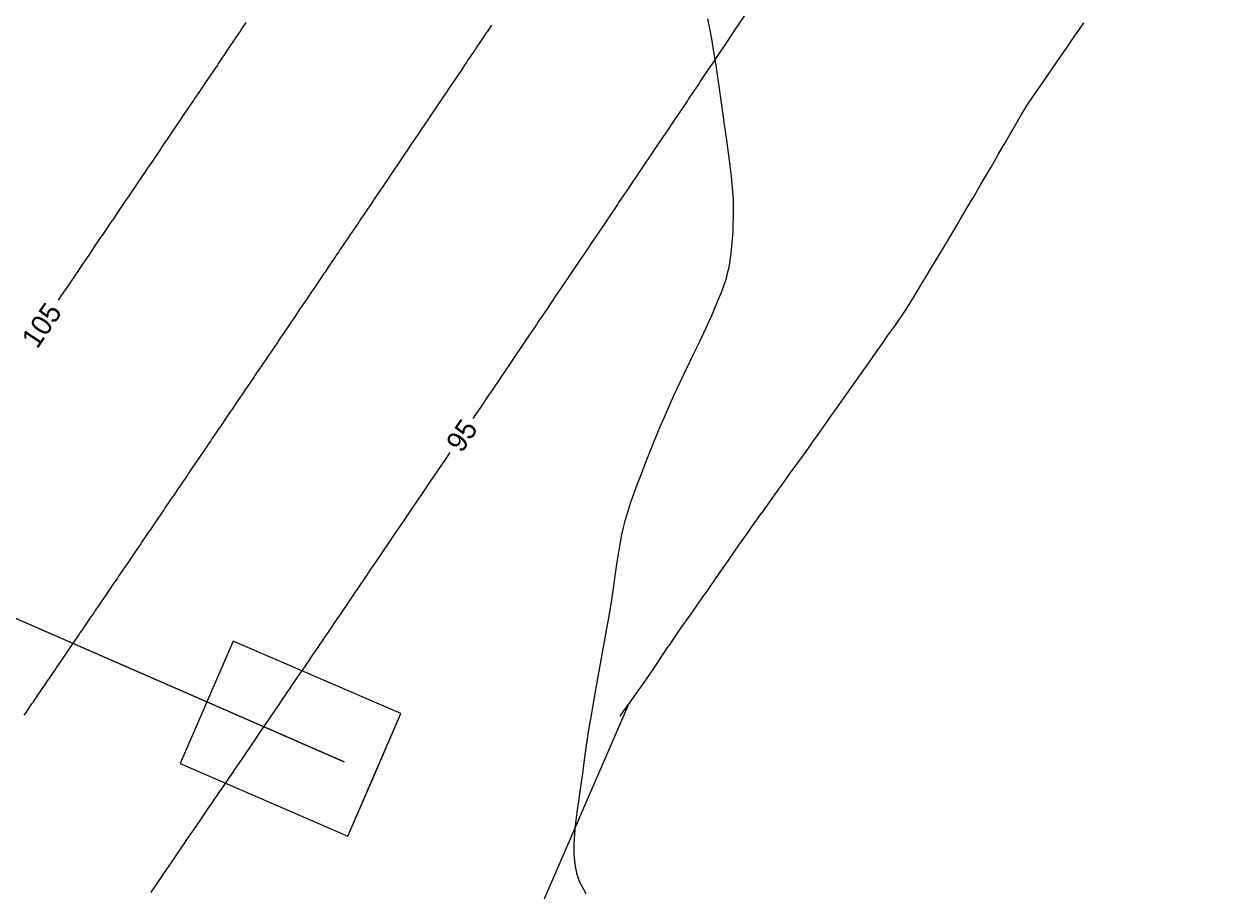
# Model space of a CAD drawing. Extents: x 1752788 to 1754108, y 472767 to 474963.
# Drawn here: x 1753280 to 1753338.7, y 473747.6 to 473789.9 of the extents above; entities that cross this region are included whole.
import ezdxf

# ---------------------------------------------------------------- set-up
doc = ezdxf.new("R2010")
doc.units = 0
for name, color, linetype in [('D_Drainage_Culvert', 7, 'Continuous'), ('D_Roadway_Centerline', 7, 'Continuous'), ('D_Slope_ClearingLimitLine', 7, 'Continuous'), ('Default', 7, 'Continuous'), ('M_Drainage_Ditch_Line', 7, 'Continuous'), ('PATTERNING', 7, 'Continuous'), ('S_Contours_Major', 7, 'Continuous')]:
    doc.layers.add(name, color=color, linetype=linetype)

msp = doc.modelspace()

# ---------------------------------------------------------------- linework, layer by layer
at = {"layer": 'D_Drainage_Culvert'}
msp.add_line((1753148.958, 473817.925), (1753295.6, 473753.923), dxfattribs=at)
at = {"layer": 'D_Roadway_Centerline'}
msp.add_arc((1748084.974, 477769.754), 6500, 316.3419444, 334.4169444, dxfattribs=at)
at = {"layer": 'D_Slope_ClearingLimitLine'}
msp.add_line((1753303.72, 473743.478), (1753309.439, 473756.699), dxfattribs=at)
msp.add_lwpolyline([(1753309.039, 473756.141), (1753309.222, 473756.398), (1753309.581, 473756.898), (1753309.969, 473757.443), (1753310.285, 473757.901), (1753310.725, 473758.55), (1753310.889, 473758.794), (1753311.387, 473759.533), (1753311.44, 473759.61), (1753311.966, 473760.382), (1753312.498, 473761.141), (1753312.608, 473761.296), (1753313.089, 473761.981), (1753313.307, 473762.293), (1753313.689, 473762.842), (1753313.983, 473763.266), (1753314.265, 473763.671), (1753314.642, 473764.213), (1753314.825, 473764.475), (1753315.287, 473765.132), (1753315.371, 473765.252), (1753315.931, 473766.038), (1753315.935, 473766.044), (1753316.521, 473766.861), (1753316.599, 473766.97), (1753317.107, 473767.678), (1753317.28, 473767.918), (1753317.698, 473768.501), (1753317.966, 473768.874), (1753318.293, 473769.329), (1753318.417, 473769.503), (1753318.681, 473769.875), (1753318.915, 473770.205), (1753319.361, 473770.837), (1753319.5, 473771.032), (1753320.038, 473771.793), (1753320.084, 473771.858), (1753320.669, 473772.685), (1753320.717, 473772.753), (1753321.264, 473773.528), (1753321.406, 473773.729), (1753321.85, 473774.36), (1753322.073, 473774.676), (1753322.448, 473775.208), (1753322.962, 473775.949), (1753323.36, 473776.603), (1753323.738, 473777.226), (1753323.898, 473777.49), (1753324.357, 473778.251), (1753324.434, 473778.38), (1753324.966, 473779.265), (1753324.985, 473779.295), (1753325.505, 473780.168), (1753325.612, 473780.348), (1753326.051, 473781.093), (1753326.234, 473781.406), (1753326.585, 473782.008), (1753326.843, 473782.451), (1753327.109, 473782.91), (1753327.443, 473783.488), (1753327.624, 473783.801), (1753327.794, 473784.095), (1753328.034, 473784.511), (1753328.134, 473784.683), (1753328.577, 473785.45), (1753328.9, 473785.977), (1753329.328, 473786.597), (1753329.487, 473786.828), (1753329.902, 473787.431), (1753330.151, 473787.793), (1753330.477, 473788.265), (1753330.816, 473788.758), (1753331.051, 473789.099), (1753331.481, 473789.723), (1753331.626, 473789.934)], dxfattribs=at)
at = {"layer": 'Default'}
msp.add_line((1753295.6, 473753.923), (1753145.826, 473819.295), dxfattribs=at)
at = {"layer": 'M_Drainage_Ditch_Line'}
msp.add_lwpolyline([(1753313.289, 473790.142), (1753313.388, 473789.663), (1753313.483, 473789.152), (1753313.575, 473788.619), (1753313.663, 473788.072), (1753313.747, 473787.52), (1753313.826, 473786.972), (1753313.974, 473785.92), (1753314.105, 473784.988), (1753314.199, 473784.338), (1753314.304, 473783.605), (1753314.356, 473783.222), (1753314.405, 473782.836), (1753314.45, 473782.453), (1753314.489, 473782.078), (1753314.519, 473781.717), (1753314.54, 473781.377), (1753314.55, 473781.063), (1753314.55, 473780.772), (1753314.547, 473780.455), (1753314.538, 473780.118), (1753314.523, 473779.768), (1753314.501, 473779.41), (1753314.472, 473779.051), (1753314.434, 473778.695), (1753314.387, 473778.35), (1753314.33, 473778.021), (1753314.262, 473777.714), (1753314.183, 473777.436), (1753313.986, 473776.88), (1753313.751, 473776.286), (1753313.484, 473775.663), (1753313.193, 473775.018), (1753312.887, 473774.362), (1753312.572, 473773.703), (1753311.952, 473772.412), (1753311.662, 473771.797), (1753311.396, 473771.214), (1753311.162, 473770.673), (1753310.997, 473770.279), (1753310.634, 473769.395), (1753310.442, 473768.921), (1753310.249, 473768.434), (1753310.057, 473767.942), (1753309.872, 473767.452), (1753309.697, 473766.972), (1753309.535, 473766.508), (1753309.391, 473766.068), (1753309.269, 473765.66), (1753309.187, 473765.343), (1753309.11, 473764.996), (1753309.04, 473764.626), (1753308.973, 473764.239), (1753308.911, 473763.841), (1753308.852, 473763.44), (1753308.69, 473762.277), (1753308.638, 473761.924), (1753308.587, 473761.601), (1753308.473, 473760.944), (1753308.347, 473760.232), (1753307.921, 473757.888), (1753307.776, 473757.077), (1753307.636, 473756.272), (1753307.505, 473755.485), (1753307.386, 473754.728), (1753307.284, 473754.012), (1753307.201, 473753.352), (1753307.146, 473752.932), (1753307.078, 473752.473), (1753307.004, 473751.982), (1753306.931, 473751.469), (1753306.865, 473750.945), (1753306.815, 473750.419), (1753306.788, 473749.901), (1753306.79, 473749.4), (1753306.829, 473748.926), (1753306.911, 473748.49), (1753307.046, 473748.1), (1753307.369, 473747.504)], dxfattribs=at)
at = {"layer": 'PATTERNING'}
for points in [[(1753297.068, 473753.287), (1753298.358, 473756.27), (1753290.19, 473759.804), (1753287.609, 473753.838), (1753295.778, 473750.304)], [(1753287.609, 473753.838), (1753295.778, 473750.304), (1753298.358, 473756.27), (1753290.19, 473759.804)]]:
    msp.add_lwpolyline(points, close=True, dxfattribs=at)
at = {"layer": 'S_Contours_Major'}
for points in [[(1753301.875, 473770.646), (1753302.124, 473771.013), (1753302.182, 473771.099), (1753302.691, 473771.853), (1753302.749, 473771.938), (1753303.259, 473772.692), (1753303.317, 473772.778), (1753303.826, 473773.531), (1753303.884, 473773.617), (1753304.392, 473774.37), (1753304.451, 473774.457), (1753304.959, 473775.209), (1753305.018, 473775.296), (1753305.526, 473776.048), (1753305.585, 473776.136), (1753306.092, 473776.887), (1753306.152, 473776.976), (1753306.659, 473777.727), (1753306.718, 473777.815), (1753306.815, 473777.959), (1753307.238, 473778.587), (1753307.283, 473778.652), (1753307.791, 473779.406), (1753307.851, 473779.495), (1753308.357, 473780.246), (1753308.417, 473780.335), (1753308.923, 473781.086), (1753308.983, 473781.175), (1753309.488, 473781.926), (1753309.549, 473782.016), (1753310.054, 473782.766), (1753310.115, 473782.856), (1753310.62, 473783.606), (1753310.681, 473783.696), (1753311.185, 473784.446), (1753311.246, 473784.537), (1753311.751, 473785.287), (1753311.811, 473785.377), (1753312.317, 473786.128), (1753312.376, 473786.217), (1753312.882, 473786.97), (1753312.941, 473787.058), (1753313.448, 473787.812), (1753313.506, 473787.898), (1753314.014, 473788.654), (1753314.071, 473788.739), (1753314.579, 473789.496), (1753314.635, 473789.579), (1753315.145, 473790.339)], [(1753302.771, 473789.823), (1753302.738, 473789.774), (1753302.678, 473789.685), (1753302.559, 473789.507), (1753302.519, 473789.447), (1753302.174, 473788.935), (1753302.114, 473788.846), (1753301.994, 473788.668), (1753301.954, 473788.609), (1753301.609, 473788.096), (1753301.549, 473788.007), (1753301.43, 473787.83), (1753301.39, 473787.77), (1753301.044, 473787.257), (1753300.984, 473787.168), (1753300.865, 473786.991), (1753300.825, 473786.932), (1753300.479, 473786.418), (1753300.419, 473786.33), (1753300.3, 473786.153), (1753300.26, 473786.094), (1753299.914, 473785.579), (1753299.854, 473785.491), (1753299.735, 473785.314), (1753299.695, 473785.255), (1753299.345, 473784.735), (1753299.296, 473784.663), (1753299.199, 473784.52), (1753299.167, 473784.472), (1753298.865, 473784.023), (1753298.831, 473783.974), (1753298.744, 473783.845), (1753298.624, 473783.667), (1753298.565, 473783.579), (1753298.217, 473783.064), (1753298.158, 473782.976), (1753298.039, 473782.8), (1753298, 473782.741), (1753297.651, 473782.225), (1753297.592, 473782.137), (1753297.474, 473781.962), (1753297.434, 473781.903), (1753297.085, 473781.387), (1753297.026, 473781.299), (1753296.908, 473781.124), (1753296.869, 473781.066), (1753296.519, 473780.548), (1753296.46, 473780.461), (1753296.342, 473780.286), (1753296.303, 473780.228), (1753295.953, 473779.71), (1753295.894, 473779.623), (1753295.777, 473779.448), (1753295.737, 473779.39), (1753295.387, 473778.872), (1753295.328, 473778.785), (1753295.211, 473778.611), (1753295.171, 473778.553), (1753294.82, 473778.034), (1753294.762, 473777.947), (1753294.644, 473777.773), (1753294.605, 473777.715), (1753294.254, 473777.196), (1753294.195, 473777.109), (1753294.078, 473776.935), (1753294.039, 473776.878), (1753293.687, 473776.358), (1753293.629, 473776.271), (1753293.511, 473776.098), (1753293.472, 473776.04), (1753293.12, 473775.52), (1753293.062, 473775.433), (1753292.945, 473775.26), (1753292.906, 473775.203), (1753292.553, 473774.682), (1753292.495, 473774.596), (1753292.378, 473774.423), (1753292.339, 473774.366), (1753291.986, 473773.844), (1753291.928, 473773.758), (1753291.811, 473773.586), (1753291.772, 473773.528), (1753291.419, 473773.007), (1753291.361, 473772.921), (1753291.244, 473772.748), (1753291.205, 473772.691), (1753290.852, 473772.169), (1753290.793, 473772.083), (1753290.677, 473771.911), (1753290.638, 473771.853), (1753290.283, 473771.331), (1753290.227, 473771.248), (1753290.115, 473771.083), (1753290.078, 473771.028), (1753289.718, 473770.497), (1753289.693, 473770.46), (1753289.561, 473770.266), (1753289.503, 473770.18), (1753289.149, 473769.657), (1753289.091, 473769.572), (1753288.974, 473769.4), (1753288.936, 473769.343), (1753288.581, 473768.82), (1753288.523, 473768.735), (1753288.407, 473768.564), (1753288.368, 473768.507), (1753288.013, 473767.983), (1753287.955, 473767.898), (1753287.839, 473767.727), (1753287.8, 473767.67), (1753287.444, 473767.146), (1753287.387, 473767.061), (1753287.271, 473766.891), (1753287.233, 473766.834), (1753286.876, 473766.309), (1753286.818, 473766.224), (1753286.703, 473766.054), (1753286.665, 473765.998), (1753286.308, 473765.472), (1753286.25, 473765.387), (1753286.135, 473765.218), (1753286.097, 473765.161), (1753285.739, 473764.635), (1753285.682, 473764.551), (1753285.567, 473764.381), (1753285.528, 473764.325), (1753285.17, 473763.798), (1753285.113, 473763.714), (1753284.998, 473763.545), (1753284.96, 473763.489), (1753284.601, 473762.962), (1753284.544, 473762.878), (1753284.43, 473762.709), (1753284.392, 473762.653), (1753284.032, 473762.125), (1753283.975, 473762.041), (1753283.861, 473761.873), (1753283.823, 473761.817), (1753283.463, 473761.289), (1753283.406, 473761.205), (1753283.292, 473761.037), (1753283.254, 473760.981), (1753282.894, 473760.452), (1753282.837, 473760.369), (1753282.723, 473760.201), (1753282.685, 473760.146), (1753282.325, 473759.616), (1753282.268, 473759.532), (1753282.154, 473759.365), (1753282.116, 473759.31), (1753281.755, 473758.78), (1753281.698, 473758.696), (1753281.585, 473758.53), (1753281.547, 473758.474), (1753281.185, 473757.943), (1753281.129, 473757.86), (1753281.015, 473757.694), (1753280.978, 473757.639), (1753280.593, 473757.074), (1753280.525, 473756.975), (1753280.402, 473756.793), (1753280.368, 473756.744), (1753280.046, 473756.271), (1753279.989, 473756.189)], [(1753281.671, 473776.416), (1753281.771, 473776.563), (1753281.793, 473776.596), (1753282.012, 473776.919), (1753282.076, 473777.014), (1753282.141, 473777.109), (1753282.302, 473777.347), (1753282.399, 473777.49), (1753282.598, 473777.784), (1753282.665, 473777.883), (1753282.867, 473778.182), (1753282.968, 473778.331), (1753283.164, 473778.62), (1753283.232, 473778.719), (1753283.434, 473779.018), (1753283.535, 473779.167), (1753283.73, 473779.456), (1753283.798, 473779.555), (1753284, 473779.854), (1753284.101, 473780.003), (1753284.296, 473780.292), (1753284.364, 473780.391), (1753284.566, 473780.69), (1753284.667, 473780.84), (1753284.862, 473781.128), (1753284.929, 473781.227), (1753285.132, 473781.527), (1753285.233, 473781.677), (1753285.427, 473781.964), (1753285.495, 473782.063), (1753285.698, 473782.363), (1753285.799, 473782.513), (1753285.993, 473782.8), (1753286.061, 473782.9), (1753286.264, 473783.2), (1753286.365, 473783.35), (1753286.558, 473783.636), (1753286.626, 473783.736), (1753286.829, 473784.037), (1753286.931, 473784.187), (1753287.123, 473784.472), (1753287.191, 473784.572), (1753287.395, 473784.873), (1753287.496, 473785.024), (1753287.688, 473785.308), (1753287.756, 473785.409), (1753287.96, 473785.71), (1753288.062, 473785.861), (1753288.253, 473786.144), (1753288.321, 473786.245), (1753288.525, 473786.547), (1753288.627, 473786.698), (1753288.818, 473786.981), (1753288.886, 473787.081), (1753289.09, 473787.384), (1753289.192, 473787.535), (1753289.382, 473787.817), (1753289.451, 473787.918), (1753289.655, 473788.221), (1753289.757, 473788.373), (1753289.947, 473788.653), (1753290.015, 473788.755), (1753290.22, 473789.058), (1753290.322, 473789.21), (1753290.511, 473789.49), (1753290.579, 473789.591), (1753290.614, 473789.642), (1753290.825, 473789.956)], [(1753286.184, 473747.557), (1753286.236, 473747.633), (1753286.755, 473748.393), (1753286.808, 473748.47), (1753287.326, 473749.23), (1753287.379, 473749.307), (1753287.897, 473750.067), (1753287.95, 473750.144), (1753288.412, 473750.822), (1753288.459, 473750.891), (1753288.512, 473750.969), (1753289.038, 473751.741), (1753289.091, 473751.819), (1753289.609, 473752.578), (1753289.662, 473752.656), (1753290.179, 473753.415), (1753290.233, 473753.494), (1753290.749, 473754.252), (1753290.803, 473754.331), (1753291.319, 473755.089), (1753291.373, 473755.169), (1753291.889, 473755.926), (1753291.943, 473756.007), (1753292.458, 473756.764), (1753292.513, 473756.844), (1753293.028, 473757.601), (1753293.083, 473757.682), (1753293.597, 473758.439), (1753293.653, 473758.52), (1753294.167, 473759.276), (1753294.222, 473759.358), (1753294.736, 473760.114), (1753294.792, 473760.196), (1753295.305, 473760.952), (1753295.361, 473761.035), (1753295.874, 473761.79), (1753295.93, 473761.873), (1753296.442, 473762.628), (1753296.499, 473762.711), (1753297.011, 473763.466), (1753297.068, 473763.55), (1753297.579, 473764.304), (1753297.65, 473764.407), (1753298.15, 473765.145), (1753298.205, 473765.226), (1753298.716, 473765.98), (1753298.774, 473766.066), (1753299.284, 473766.819), (1753299.342, 473766.904), (1753299.853, 473767.658), (1753299.91, 473767.743), (1753300.421, 473768.497), (1753300.478, 473768.582), (1753300.759, 473768.996)]]:
    msp.add_lwpolyline(points, dxfattribs=at)

# ---------------------------------------------------------------- texts
for s, rotation, p in [('105', 55.85225, (1753280.636, 473774.003)), ('95', 55.91413, (1753301.318, 473768.934))]:
    msp.add_text(s, height=0.996, rotation=rotation, dxfattribs=at).set_placement(p)

doc.saveas('drawing.dxf')
